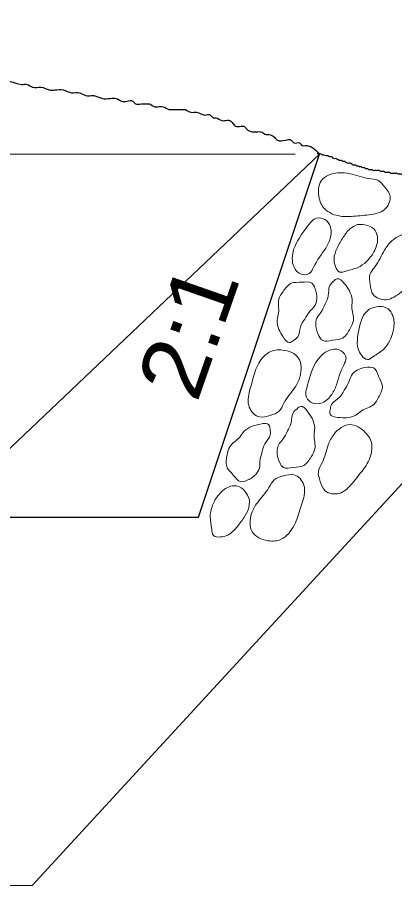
# Model space of a CAD drawing. Extents: x 1043.1 to 1101.1, y 672.4 to 716.4.
# Drawn here: x 1098.885 to 1099.82, y 702.97 to 705.121 of the extents above; entities that cross this region are included whole.
import ezdxf

# ---------------------------------------------------------------- set-up
doc = ezdxf.new("R2010")
doc.units = 0
doc.header["$LTSCALE"] = 0.064
doc.layers.add('1', color=7, linetype='Continuous', lineweight=13)

msp = doc.modelspace()

# ---------------------------------------------------------------- linework, layer by layer
at = {"layer": '1'}
for p, q in [((1099.57342, 704.782), (1098.254, 704.782)), ((1098.92183, 702.96983), (1100.15133, 704.30633)), ((1098.36767, 702.96983), (1098.92183, 702.96983))]:
    msp.add_line(p, q, dxfattribs=at)
at = {"layer": '1', "lineweight": 25}
for p, q in [((1099.63333, 704.782), (1098.67192, 703.86842)), ((1099.3335, 703.8825), (1099.63333, 704.782)), ((1096.15517, 703.8825), (1099.3335, 703.8825))]:
    msp.add_line(p, q, dxfattribs=at)
for points in [[(1097.41433, 705.12), (1097.435, 705.12), (1097.45575, 705.12), (1097.497, 705.11317), (1097.52467, 705.11317), (1097.55225, 705.10625), (1097.57283, 705.10625), (1097.60033, 705.09933), (1097.63475, 705.09933), (1097.66925, 705.09933), (1097.68992, 705.09242), (1097.7105, 705.09242), (1097.73817, 705.09242), (1097.75883, 705.0855), (1097.77267, 705.0855), (1097.8, 705.0855), (1097.82075, 705.07867), (1097.84142, 705.07867), (1097.862, 705.07867), (1097.88967, 705.07175), (1097.91033, 705.07175), (1097.931, 705.07175), (1097.95167, 705.06483), (1097.97233, 705.06483), (1098.02733, 705.05792), (1098.048, 705.05792), (1098.07567, 705.05792), (1098.11, 705.051), (1098.13075, 705.051), (1098.172, 705.04417), (1098.1995, 705.04417), (1098.22717, 705.04417), (1098.24775, 705.03725), (1098.28225, 705.03725), (1098.30983, 705.03033), (1098.33733, 705.03033), (1098.358, 705.03033), (1098.37875, 705.02342), (1098.40617, 705.02342), (1098.42683, 705.02342), (1098.4475, 705.0165), (1098.46817, 705.0165), (1098.49575, 705.0165), (1098.5095, 705.0165), (1098.53025, 705.00967), (1098.55775, 705.00967), (1098.57842, 705.00275), (1098.599, 705.00275), (1098.61967, 704.99583), (1098.63342, 704.99583), (1098.65417, 704.99583), (1098.67483, 704.989), (1098.69542, 704.989), (1098.70925, 704.98217), (1098.72992, 704.98217), (1098.75067, 704.98217), (1098.77125, 704.97525), (1098.78492, 704.97525), (1098.79875, 704.96833), (1098.81942, 704.96833), (1098.84, 704.96833), (1098.85383, 704.96142), (1098.86767, 704.96142), (1098.89525, 704.9545), (1098.909, 704.9545), (1098.92275, 704.94767), (1098.94342, 704.94767), (1098.96417, 704.94075), (1098.97792, 704.94075), (1098.99842, 704.94075), (1099.01917, 704.93383), (1099.03983, 704.93383), (1099.05367, 704.92692), (1099.07425, 704.92692), (1099.09492, 704.92), (1099.11567, 704.92), (1099.12942, 704.92), (1099.14317, 704.91317), (1099.15692, 704.91317), (1099.17075, 704.91317), (1099.17767, 704.90625), (1099.19142, 704.90625), (1099.19825, 704.90625), (1099.212, 704.90625), (1099.22575, 704.89933), (1099.23267, 704.89933), (1099.24642, 704.89933), (1099.26025, 704.89242), (1099.26717, 704.89242), (1099.28092, 704.89242), (1099.3015, 704.89242)], [(1099.3015, 704.89242), (1099.31533, 704.8855), (1099.32917, 704.8855), (1099.34983, 704.87867), (1099.36367, 704.87867), (1099.37042, 704.87175), (1099.37733, 704.87175), (1099.39117, 704.86483), (1099.39792, 704.86483), (1099.41175, 704.86483), (1099.41867, 704.85792), (1099.4255, 704.851), (1099.43933, 704.851), (1099.44617, 704.851), (1099.453, 704.84417), (1099.46683, 704.83725), (1099.47375, 704.83725), (1099.48067, 704.83725), (1099.4875, 704.83725), (1099.50133, 704.83033), (1099.50825, 704.83033), (1099.52192, 704.82342), (1099.52883, 704.81667), (1099.5495, 704.81667), (1099.56333, 704.81667), (1099.57025, 704.80975), (1099.57717, 704.80975), (1099.584, 704.80975), (1099.59083, 704.80283), (1099.59775, 704.80283), (1099.63333, 704.78267)], [(1099.63333, 704.782), (1099.62933, 704.78275), (1099.62933, 704.785), (1099.62933, 704.78275), (1099.63167, 704.78275), (1099.63625, 704.78275), (1099.64075, 704.78042), (1099.643, 704.78042), (1099.64983, 704.77817), (1099.65442, 704.77817), (1099.65892, 704.77592), (1099.6635, 704.77592), (1099.66575, 704.77367), (1099.67033, 704.77133), (1099.67483, 704.77133), (1099.67717, 704.769), (1099.67942, 704.769), (1099.68175, 704.76683), (1099.68625, 704.76683), (1099.69083, 704.7645), (1099.69533, 704.7645), (1099.69767, 704.76225), (1099.70217, 704.75992), (1099.70675, 704.75992), (1099.709, 704.75992), (1099.7135, 704.75767), (1099.71583, 704.75542), (1099.72033, 704.75542), (1099.72267, 704.75542), (1099.72492, 704.75317), (1099.7295, 704.75317), (1099.73175, 704.75083), (1099.734, 704.75083), (1099.73633, 704.75083), (1099.74083, 704.7485), (1099.74317, 704.7485), (1099.74542, 704.7485), (1099.74775, 704.74625), (1099.74992, 704.74625), (1099.75225, 704.74625), (1099.7545, 704.744), (1099.75683, 704.744), (1099.759, 704.744), (1099.76133, 704.744), (1099.76367, 704.744), (1099.76592, 704.74175), (1099.77042, 704.74175), (1099.77275, 704.74175), (1099.77725, 704.74175), (1099.78183, 704.74175), (1099.78417, 704.73942), (1099.78867, 704.73942), (1099.79325, 704.73942), (1099.79542, 704.73717), (1099.8, 704.73717), (1099.80225, 704.73717), (1099.80675, 704.73717), (1099.809, 704.73492), (1099.81133, 704.73492), (1099.8135, 704.73492), (1099.81817, 704.73492), (1099.82267, 704.73492), (1099.82492, 704.73492), (1099.82725, 704.73267), (1099.8295, 704.73267), (1099.83175, 704.73267), (1099.83633, 704.73267), (1099.83867, 704.73033), (1099.84317, 704.73033), (1099.84775, 704.73033), (1099.84992, 704.728), (1099.8545, 704.728), (1099.859, 704.728), (1099.86367, 704.72575), (1099.86817, 704.72575), (1099.87042, 704.72575), (1099.87725, 704.7235), (1099.88183, 704.7235), (1099.88867, 704.7235), (1099.8955, 704.72125), (1099.9, 704.71892), (1099.90233, 704.71892), (1099.90683, 704.71892), (1099.91142, 704.71667), (1099.91375, 704.71667), (1099.91592, 704.71667), (1099.9205, 704.71433), (1099.92283, 704.71433), (1099.92733, 704.71217), (1099.92967, 704.71217), (1099.93417, 704.71217)]]:
    msp.add_spline(points, degree=3, dxfattribs=at)
at = {"layer": '1'}
for points in [[(1099.6695, 704.63175), (1099.64925, 704.64325), (1099.63292, 704.67217), (1099.63792, 704.716), (1099.67892, 704.7355), (1099.709, 704.73317), (1099.75492, 704.7215), (1099.778, 704.71717), (1099.79542, 704.70017), (1099.80825, 704.67717), (1099.79475, 704.64475), (1099.77667, 704.63533), (1099.73425, 704.62933), (1099.6895, 704.62767), (1099.6695, 704.63175)], [(1099.64942, 704.549), (1099.66075, 704.57642), (1099.65783, 704.60783), (1099.64217, 704.62192), (1099.6215, 704.62125), (1099.60867, 704.609), (1099.57225, 704.55242), (1099.56833, 704.50725), (1099.58667, 704.48517), (1099.60792, 704.48583), (1099.61875, 704.50142), (1099.64942, 704.549)], [(1099.72725, 704.60717), (1099.709, 704.59675), (1099.69242, 704.57617), (1099.67717, 704.54917), (1099.66942, 704.52217), (1099.67283, 704.50375), (1099.68325, 704.48967), (1099.69942, 704.49225), (1099.72833, 704.50092), (1099.74942, 704.51542), (1099.76833, 704.54017), (1099.77733, 704.573), (1099.77167, 704.59225), (1099.75192, 704.60525), (1099.72725, 704.60717)], [(1099.895, 704.5025), (1099.90083, 704.52517), (1099.89117, 704.557), (1099.856, 704.58383), (1099.81367, 704.56775), (1099.79467, 704.54433), (1099.77117, 704.50317), (1099.75833, 704.4835), (1099.75867, 704.459), (1099.76633, 704.43392), (1099.799, 704.42125), (1099.81833, 704.42783), (1099.85217, 704.45433), (1099.88425, 704.48542), (1099.895, 704.5025)], [(1099.53292, 704.34775), (1099.54325, 704.32892), (1099.55933, 704.315), (1099.56875, 704.31992), (1099.57967, 704.32933), (1099.58633, 704.35417), (1099.59675, 704.37317), (1099.60992, 704.39275), (1099.62125, 704.40517), (1099.62675, 704.42342), (1099.62225, 704.44975), (1099.61417, 704.46225), (1099.59, 704.46442), (1099.56342, 704.46183), (1099.54317, 704.44133), (1099.53267, 704.42283), (1099.53217, 704.38842), (1099.52875, 704.37092), (1099.53292, 704.34775)], [(1099.70742, 704.44417), (1099.69483, 704.46142), (1099.677, 704.47325), (1099.66825, 704.467), (1099.65875, 704.45642), (1099.65533, 704.431), (1099.64742, 704.41075), (1099.63683, 704.3895), (1099.62725, 704.37583), (1099.62425, 704.35692), (1099.632, 704.33142), (1099.6415, 704.32), (1099.66575, 704.321), (1099.69183, 704.32692), (1099.70942, 704.35), (1099.71733, 704.36975), (1099.7135, 704.40383), (1099.71442, 704.42167), (1099.70742, 704.44417)], [(1099.75675, 704.39817), (1099.74283, 704.3825), (1099.7335, 704.35775), (1099.72775, 704.32725), (1099.72917, 704.29933), (1099.738, 704.28292), (1099.75242, 704.27283), (1099.76692, 704.28042), (1099.79167, 704.298), (1099.80683, 704.31833), (1099.81692, 704.34775), (1099.815, 704.38175), (1099.8035, 704.39825), (1099.78075, 704.40425), (1099.75675, 704.39817)], [(1099.49117, 704.27642), (1099.50917, 704.29142), (1099.54192, 704.2965), (1099.58142, 704.27667), (1099.58525, 704.23133), (1099.57242, 704.20392), (1099.54542, 704.16517), (1099.53333, 704.14517), (1099.51125, 704.13475), (1099.48517, 704.13075), (1099.4595, 704.15492), (1099.45692, 704.175), (1099.46633, 704.21683), (1099.48033, 704.25933), (1099.49117, 704.27642)], [(1099.67433, 704.20617), (1099.65933, 704.18067), (1099.63267, 704.16375), (1099.61192, 704.1675), (1099.59992, 704.18442), (1099.60192, 704.20217), (1099.62475, 704.2655), (1099.65825, 704.29617), (1099.68692, 704.29492), (1099.69933, 704.27742), (1099.69342, 704.25933), (1099.67433, 704.20617)], [(1099.70067, 704.12875), (1099.67925, 704.1295), (1099.65967, 704.13767), (1099.65983, 704.14825), (1099.66333, 704.162), (1099.6825, 704.17917), (1099.69492, 704.197), (1099.7065, 704.21767), (1099.7125, 704.23333), (1099.7265, 704.24642), (1099.752, 704.254), (1099.76683, 704.2525), (1099.7795, 704.23183), (1099.78917, 704.20692), (1099.77992, 704.1795), (1099.76792, 704.16175), (1099.7375, 704.146), (1099.72325, 704.13525), (1099.70067, 704.12875)], [(1099.61575, 704.1265), (1099.604, 704.14433), (1099.58692, 704.15692), (1099.57792, 704.15117), (1099.56783, 704.14117), (1099.56317, 704.11583), (1099.55433, 704.096), (1099.54267, 704.07542), (1099.53242, 704.06225), (1099.52842, 704.04342), (1099.53492, 704.01767), (1099.544, 704.00575), (1099.56825, 704.00567), (1099.5945, 704.01033), (1099.613, 704.03233), (1099.622, 704.05175), (1099.61992, 704.08592), (1099.62167, 704.10375), (1099.61575, 704.1265)], [(1099.46642, 704.108), (1099.48717, 704.11325), (1099.50833, 704.111), (1099.51117, 704.10067), (1099.51167, 704.08633), (1099.49817, 704.0645), (1099.49125, 704.044), (1099.486, 704.02083), (1099.48467, 704.00417), (1099.47492, 703.98775), (1099.45267, 703.97325), (1099.438, 703.9705), (1099.41992, 703.98675), (1099.40367, 704.00783), (1099.40483, 704.03675), (1099.41125, 704.057), (1099.436, 704.08083), (1099.44667, 704.09525), (1099.46642, 704.108)], [(1099.7615, 704.03892), (1099.76317, 704.06225), (1099.74767, 704.09183), (1099.70817, 704.11175), (1099.6695, 704.08817), (1099.655, 704.0615), (1099.63975, 704.01675), (1099.63067, 703.99517), (1099.63533, 703.97125), (1099.64767, 703.94783), (1099.68217, 703.94142), (1099.7, 703.95142), (1099.72817, 703.98367), (1099.75417, 704.02), (1099.7615, 704.03892)], [(1099.55717, 703.842), (1099.53867, 703.82783), (1099.50542, 703.82433), (1099.46692, 703.84625), (1099.46533, 703.89167), (1099.4795, 703.91833), (1099.50833, 703.95583), (1099.52142, 703.97542), (1099.544, 703.98467), (1099.57017, 703.98742), (1099.59475, 703.96217), (1099.59617, 703.94175), (1099.58492, 703.90042), (1099.56883, 703.85867), (1099.55717, 703.842)], [(1099.45983, 703.92567), (1099.45783, 703.90475), (1099.44592, 703.881), (1099.42742, 703.85617), (1099.406, 703.838), (1099.38783, 703.8335), (1099.37083, 703.83725), (1099.36642, 703.85317), (1099.36267, 703.88317), (1099.36725, 703.90825), (1099.38192, 703.93567), (1099.40825, 703.95725), (1099.42817, 703.96), (1099.44817, 703.94733), (1099.45983, 703.92567)]]:
    msp.add_spline(points, degree=3, dxfattribs=at)

# ---------------------------------------------------------------- texts
at = {"layer": '1', "width": 1.1}
msp.add_text('2:1', height=0.16, rotation=70.76, dxfattribs=at).set_placement((1099.32975, 704.16317))

doc.saveas('drawing.dxf')
